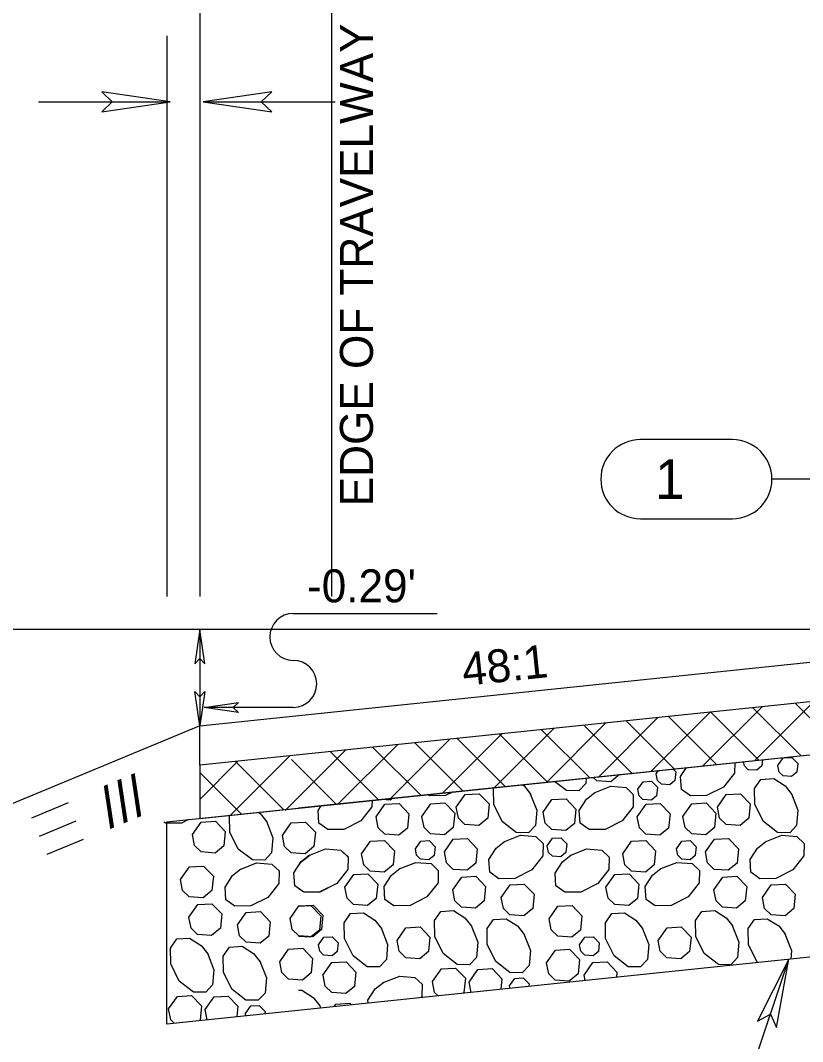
# Model space of a CAD drawing. Extents: x 6561 to 6787, y 19927 to 20919.
# Drawn here: x 6684.34 to 6696.19, y 20747.4 to 20762.88 of the extents above; entities that cross this region are included whole.
import ezdxf

# ---------------------------------------------------------------- set-up
doc = ezdxf.new("R2010")
doc.units = 0
for name, color, linetype in [('Level 1', 7, 'Continuous'), ('Level 3', 7, 'Continuous'), ('Level 5', 7, 'Continuous'), ('Level 7', 7, 'Continuous'), ('Level 8', 7, 'Continuous')]:
    doc.layers.add(name, color=color, linetype=linetype)

msp = doc.modelspace()

# ---------------------------------------------------------------- linework, layer by layer
at = {"layer": 'Level 1'}
for p, q in [((6687.057, 20764.65), (6687.057, 20754.15)), ((6689.057, 20764.65), (6689.057, 20754.15)), ((6686.557, 20762.65), (6686.557, 20754.15)), ((6684.612, 20761.65), (6686.612, 20761.65)), ((6687.112, 20761.65), (6689.112, 20761.65)), ((6688.476, 20753.894), (6690.658, 20753.894)), ((6779.047, 20753.65), (6628.473, 20753.65)), ((6687.057, 20753.65), (6687.057, 20752.192)), ((6688.476, 20752.47), (6687.127, 20752.47))]:
    msp.add_line(p, q, dxfattribs=at)
for points in [[(6686.612, 20761.65), (6685.573, 20761.8), (6685.733, 20761.65), (6685.573, 20761.5)], [(6687.112, 20761.65), (6688.151, 20761.5), (6687.991, 20761.65), (6688.151, 20761.8)], [(6687.057, 20753.65), (6686.985, 20753.13), (6687.059, 20753.211), (6687.135, 20753.131)], [(6687.057, 20752.192), (6686.985, 20752.711), (6687.059, 20752.631), (6687.135, 20752.711)], [(6687.127, 20752.47), (6687.647, 20752.542), (6687.566, 20752.467), (6687.646, 20752.392)]]:
    msp.add_lwpolyline(points, close=True, dxfattribs=at)
for centre, start, end in [((6688.476, 20753.538), 90, 270), ((6688.476, 20752.826), 270, 90)]:
    msp.add_arc(centre, 0.356, start, end, dxfattribs=at)
at = {"layer": 'Level 3'}
for p, q in [((6701.057, 20753.05), (6687.057, 20751.592)), ((6696.371, 20752.562), (6695.473, 20751.664)), ((6696.811, 20751.803), (6696.082, 20752.532)), ((6694.792, 20752.397), (6693.894, 20751.499)), ((6695.582, 20752.48), (6694.684, 20751.582)), ((6695.53, 20751.67), (6694.802, 20752.398)), ((6696.171, 20751.737), (6695.442, 20752.465)), ((6687.057, 20750.787), (6701.057, 20752.246)), ((6693.214, 20752.233), (6692.316, 20751.335)), ((6694.003, 20752.315), (6693.105, 20751.417)), ((6694.249, 20751.536), (6693.521, 20752.265)), ((6694.89, 20751.603), (6694.161, 20752.332)), ((6691.635, 20752.068), (6690.737, 20751.171)), ((6692.424, 20752.151), (6691.526, 20751.253)), ((6692.328, 20751.336), (6691.6, 20752.065)), ((6692.969, 20751.403), (6692.24, 20752.131)), ((6693.609, 20751.47), (6692.88, 20752.198)), ((6690.056, 20751.904), (6689.158, 20751.006)), ((6690.846, 20751.986), (6689.948, 20751.088)), ((6691.047, 20751.203), (6690.319, 20751.931)), ((6691.688, 20751.27), (6690.959, 20751.998)), ((6689.267, 20751.822), (6688.352, 20750.907)), ((6689.767, 20751.07), (6689.038, 20751.798)), ((6690.407, 20751.136), (6689.678, 20751.865)), ((6687.635, 20751.652), (6687.057, 20751.074)), ((6687.057, 20751.592), (6687.057, 20750.787)), ((6688.424, 20751.734), (6687.526, 20750.836)), ((6688.328, 20750.92), (6687.6, 20751.648)), ((6689.126, 20751.003), (6688.449, 20751.68)), ((6687.688, 20750.853), (6687.057, 20751.484))]:
    msp.add_line(p, q, dxfattribs=at)
at = {"layer": 'Level 5'}
for p, q in [((6686.557, 20750.735), (6701.057, 20752.246)), ((6688.557, 20750.944), (6701.057, 20752.246)), ((6686.557, 20747.669), (6686.557, 20750.735)), ((6701.057, 20749.179), (6686.557, 20747.669))]:
    msp.add_line(p, q, dxfattribs=at)
for points in [[(6695.166, 20751.632), (6695.163, 20751.474), (6694.996, 20751.261), (6694.738, 20751.133), (6694.496, 20751.128), (6694.359, 20751.225), (6694.346, 20751.419), (6694.434, 20751.556)], [(6695.588, 20751.676), (6695.578, 20751.582), (6695.499, 20751.516), (6695.371, 20751.525), (6695.312, 20751.583), (6695.299, 20751.646)], [(6695.822, 20751.588), (6695.902, 20751.703), (6696.031, 20751.71), (6696.121, 20751.617), (6696.108, 20751.487), (6696.028, 20751.421), (6695.901, 20751.43), (6695.841, 20751.488), (6695.822, 20751.588)], [(6693.418, 20751.45), (6693.287, 20751.341), (6693.075, 20751.356), (6693.021, 20751.408)], [(6693.974, 20751.462), (6694.009, 20751.511)], [(6694.232, 20751.535), (6694.273, 20751.491), (6694.261, 20751.361), (6694.181, 20751.295), (6694.054, 20751.304), (6693.994, 20751.362), (6693.975, 20751.462)], [(6691.944, 20751.296), (6691.973, 20751.278), (6692.074, 20751.151)], [(6692.915, 20751.398), (6692.908, 20751.313), (6692.804, 20751.203), (6692.616, 20751.207), (6692.436, 20751.348)], [(6693.697, 20751.229), (6693.778, 20751.343), (6693.907, 20751.351), (6693.996, 20751.258), (6693.983, 20751.128), (6693.904, 20751.062), (6693.776, 20751.071), (6693.716, 20751.129), (6693.697, 20751.229)], [(6696.025, 20751.161), (6696.125, 20750.91), (6696.105, 20750.679), (6696, 20750.569), (6695.813, 20750.572), (6695.6, 20750.739), (6695.471, 20750.997), (6695.467, 20751.239), (6695.564, 20751.376), (6695.757, 20751.389), (6695.93, 20751.278), (6696.031, 20751.151)], [(6690.889, 20751.186), (6690.781, 20751.133), (6690.538, 20751.128), (6690.512, 20751.147)], [(6690.946, 20750.956), (6691.08, 20751.148), (6691.295, 20751.16), (6691.444, 20751.005), (6691.423, 20750.788), (6691.29, 20750.678), (6691.078, 20750.694), (6690.978, 20750.79), (6690.946, 20750.956)], [(6692.068, 20751.161), (6692.167, 20750.91), (6692.147, 20750.679), (6692.043, 20750.569), (6691.855, 20750.572), (6691.642, 20750.739), (6691.514, 20750.997), (6691.509, 20751.239), (6691.518, 20751.252)], [(6693.037, 20751.174), (6693.288, 20751.274), (6693.519, 20751.254), (6693.629, 20751.149), (6693.626, 20750.962), (6693.459, 20750.749), (6693.201, 20750.62), (6692.959, 20750.616), (6692.822, 20750.713), (6692.809, 20750.906), (6692.92, 20751.079), (6693.047, 20751.181)], [(6694.903, 20750.956), (6695.038, 20751.148), (6695.252, 20751.16), (6695.402, 20751.005), (6695.38, 20750.788), (6695.247, 20750.678), (6695.035, 20750.694), (6694.936, 20750.79), (6694.903, 20750.956)], [(6689.67, 20751.059), (6689.668, 20750.962), (6689.501, 20750.749), (6689.244, 20750.62), (6689.001, 20750.616), (6688.864, 20750.713), (6688.852, 20750.906), (6688.898, 20750.979)], [(6689.731, 20750.808), (6689.865, 20751), (6690.08, 20751.012), (6690.229, 20750.857), (6690.207, 20750.64), (6690.075, 20750.53), (6689.863, 20750.545), (6689.763, 20750.642), (6689.731, 20750.808)], [(6689.983, 20751.092), (6689.946, 20751.062), (6689.819, 20751.071), (6689.815, 20751.075)], [(6690.424, 20750.816), (6690.559, 20751.007), (6690.773, 20751.02), (6690.923, 20750.865), (6690.901, 20750.648), (6690.769, 20750.538), (6690.557, 20750.553), (6690.457, 20750.65), (6690.424, 20750.816)], [(6692.261, 20750.879), (6692.396, 20751.071), (6692.61, 20751.083), (6692.76, 20750.928), (6692.738, 20750.711), (6692.605, 20750.601), (6692.393, 20750.616), (6692.294, 20750.713), (6692.261, 20750.879)], [(6693.688, 20750.808), (6693.823, 20751), (6694.037, 20751.012), (6694.186, 20750.857), (6694.165, 20750.64), (6694.032, 20750.53), (6693.82, 20750.545), (6693.721, 20750.642), (6693.688, 20750.808)], [(6694.382, 20750.816), (6694.516, 20751.007), (6694.731, 20751.02), (6694.88, 20750.865), (6694.859, 20750.648), (6694.726, 20750.538), (6694.514, 20750.553), (6694.414, 20750.65), (6694.382, 20750.816)], [(6688.068, 20750.745), (6688.167, 20750.493), (6688.147, 20750.262), (6688.043, 20750.152), (6687.855, 20750.156), (6687.642, 20750.322), (6687.514, 20750.58), (6687.509, 20750.823), (6687.518, 20750.835)], [(6687.944, 20750.88), (6687.973, 20750.862), (6688.074, 20750.735)], [(6686.889, 20750.77), (6686.781, 20750.716), (6686.538, 20750.712), (6686.512, 20750.73)], [(6686.946, 20750.54), (6687.08, 20750.731), (6687.295, 20750.743), (6687.444, 20750.589), (6687.423, 20750.372), (6687.29, 20750.261), (6687.078, 20750.277), (6686.978, 20750.374), (6686.946, 20750.54)], [(6688.312, 20750.527), (6688.446, 20750.718), (6688.661, 20750.73), (6688.81, 20750.576), (6688.789, 20750.359), (6688.656, 20750.249), (6688.444, 20750.264), (6688.344, 20750.361), (6688.312, 20750.527)], [(6691.669, 20750.43), (6691.92, 20750.53), (6692.151, 20750.51), (6692.261, 20750.406), (6692.258, 20750.218), (6692.091, 20750.005), (6691.833, 20749.876), (6691.591, 20749.872), (6691.454, 20749.969), (6691.441, 20750.162), (6691.552, 20750.335), (6691.679, 20750.437)], [(6695.626, 20750.43), (6695.878, 20750.53), (6696.109, 20750.51), (6696.219, 20750.406), (6696.215, 20750.218), (6696.048, 20750.005), (6695.791, 20749.876), (6695.548, 20749.872), (6695.412, 20749.969), (6695.399, 20750.162), (6695.509, 20750.335), (6695.636, 20750.437)], [(6689.51, 20750.248), (6689.645, 20750.44), (6689.859, 20750.452), (6690.008, 20750.297), (6689.987, 20750.08), (6689.854, 20749.97), (6689.642, 20749.985), (6689.543, 20750.082), (6689.51, 20750.248)], [(6690.326, 20750.327), (6690.407, 20750.442), (6690.535, 20750.449), (6690.625, 20750.356), (6690.612, 20750.226), (6690.532, 20750.16), (6690.405, 20750.169), (6690.345, 20750.227), (6690.326, 20750.327)], [(6690.767, 20750.277), (6690.901, 20750.469), (6691.116, 20750.481), (6691.265, 20750.326), (6691.243, 20750.109), (6691.111, 20749.999), (6690.899, 20750.014), (6690.799, 20750.111), (6690.767, 20750.277)], [(6692.323, 20750.371), (6692.403, 20750.486), (6692.532, 20750.493), (6692.622, 20750.4), (6692.609, 20750.27), (6692.529, 20750.204), (6692.402, 20750.213), (6692.342, 20750.271), (6692.323, 20750.371)], [(6693.468, 20750.248), (6693.602, 20750.44), (6693.817, 20750.452), (6693.966, 20750.297), (6693.944, 20750.08), (6693.812, 20749.97), (6693.6, 20749.985), (6693.5, 20750.082), (6693.468, 20750.248)], [(6694.283, 20750.327), (6694.364, 20750.442), (6694.493, 20750.449), (6694.582, 20750.356), (6694.569, 20750.226), (6694.49, 20750.16), (6694.363, 20750.169), (6694.303, 20750.227), (6694.283, 20750.327)], [(6694.724, 20750.277), (6694.858, 20750.469), (6695.073, 20750.481), (6695.222, 20750.326), (6695.201, 20750.109), (6695.068, 20749.999), (6694.856, 20750.014), (6694.756, 20750.111), (6694.724, 20750.277)], [(6688.712, 20750.226), (6688.964, 20750.326), (6689.195, 20750.306), (6689.305, 20750.202), (6689.301, 20750.014), (6689.134, 20749.801), (6688.877, 20749.672), (6688.634, 20749.668), (6688.498, 20749.765), (6688.485, 20749.959), (6688.595, 20750.131), (6688.722, 20750.233)], [(6688.713, 20750.224), (6688.965, 20750.323), (6689.196, 20750.304), (6689.306, 20750.199), (6689.302, 20750.012), (6689.136, 20749.799), (6688.878, 20749.67), (6688.635, 20749.666), (6688.557, 20749.721)], [(6688.557, 20750.067), (6688.597, 20750.129), (6688.724, 20750.23)], [(6692.671, 20750.224), (6692.922, 20750.323), (6693.154, 20750.304), (6693.263, 20750.199), (6693.26, 20750.012), (6693.093, 20749.799), (6692.836, 20749.67), (6692.593, 20749.666), (6692.456, 20749.763), (6692.443, 20749.956), (6692.554, 20750.129), (6692.681, 20750.23)], [(6686.767, 20749.861), (6686.901, 20750.052), (6687.116, 20750.064), (6687.265, 20749.909), (6687.243, 20749.693), (6687.111, 20749.582), (6686.899, 20749.598), (6686.799, 20749.694), (6686.767, 20749.861)], [(6687.669, 20750.014), (6687.92, 20750.113), (6688.151, 20750.093), (6688.261, 20749.989), (6688.258, 20749.801), (6688.091, 20749.588), (6687.833, 20749.46), (6687.591, 20749.455), (6687.454, 20749.552), (6687.441, 20749.746), (6687.552, 20749.919), (6687.679, 20750.02)], [(6690.08, 20750.02), (6690.332, 20750.12), (6690.563, 20750.1), (6690.672, 20749.996), (6690.669, 20749.808), (6690.502, 20749.595), (6690.245, 20749.466), (6690.002, 20749.462), (6689.865, 20749.559), (6689.852, 20749.753), (6689.963, 20749.926), (6690.09, 20750.027)], [(6694.037, 20750.02), (6694.289, 20750.12), (6694.52, 20750.1), (6694.63, 20749.996), (6694.626, 20749.808), (6694.46, 20749.595), (6694.202, 20749.466), (6693.959, 20749.462), (6693.823, 20749.559), (6693.81, 20749.753), (6693.921, 20749.926), (6694.048, 20750.027)], [(6689.257, 20749.742), (6689.392, 20749.934), (6689.606, 20749.946), (6689.755, 20749.791), (6689.734, 20749.574), (6689.601, 20749.464), (6689.389, 20749.479), (6689.29, 20749.576), (6689.257, 20749.742)], [(6690.893, 20749.705), (6691.028, 20749.896), (6691.242, 20749.908), (6691.391, 20749.754), (6691.37, 20749.537), (6691.237, 20749.426), (6691.025, 20749.442), (6690.926, 20749.538), (6690.893, 20749.705)], [(6693.215, 20749.742), (6693.349, 20749.934), (6693.564, 20749.946), (6693.713, 20749.791), (6693.691, 20749.574), (6693.559, 20749.464), (6693.347, 20749.479), (6693.247, 20749.576), (6693.215, 20749.742)], [(6694.85, 20749.705), (6694.985, 20749.896), (6695.2, 20749.908), (6695.349, 20749.754), (6695.327, 20749.537), (6695.195, 20749.426), (6694.983, 20749.442), (6694.883, 20749.538), (6694.851, 20749.705)], [(6691.628, 20749.588), (6691.763, 20749.779), (6691.977, 20749.791), (6692.127, 20749.636), (6692.105, 20749.42), (6691.972, 20749.309), (6691.76, 20749.325), (6691.661, 20749.421), (6691.628, 20749.588)], [(6695.586, 20749.588), (6695.72, 20749.779), (6695.935, 20749.791), (6696.084, 20749.636), (6696.062, 20749.42), (6695.93, 20749.309), (6695.718, 20749.325), (6695.618, 20749.421), (6695.586, 20749.588)], [(6686.893, 20749.288), (6687.028, 20749.479), (6687.242, 20749.492), (6687.391, 20749.337), (6687.37, 20749.12), (6687.237, 20749.01), (6687.025, 20749.025), (6686.926, 20749.122), (6686.893, 20749.288)], [(6688.427, 20749.268), (6688.561, 20749.459), (6688.776, 20749.471), (6688.925, 20749.317), (6688.904, 20749.1), (6688.771, 20748.99), (6688.559, 20749.005), (6688.459, 20749.102), (6688.427, 20749.268)], [(6688.557, 20749.455), (6688.744, 20749.466), (6688.893, 20749.311), (6688.872, 20749.094), (6688.739, 20748.984), (6688.557, 20748.997)], [(6692.352, 20749.262), (6692.487, 20749.454), (6692.701, 20749.466), (6692.851, 20749.311), (6692.829, 20749.094), (6692.696, 20748.984), (6692.485, 20748.999), (6692.385, 20749.096), (6692.352, 20749.262)], [(6687.628, 20749.171), (6687.763, 20749.362), (6687.977, 20749.374), (6688.127, 20749.22), (6688.105, 20749.003), (6687.972, 20748.893), (6687.76, 20748.908), (6687.661, 20749.005), (6687.628, 20749.171)], [(6689.806, 20749.127), (6689.906, 20748.876), (6689.886, 20748.645), (6689.782, 20748.535), (6689.594, 20748.538), (6689.381, 20748.705), (6689.252, 20748.963), (6689.248, 20749.205), (6689.345, 20749.342), (6689.539, 20749.355), (6689.712, 20749.244), (6689.813, 20749.117)], [(6691.173, 20749.16), (6691.273, 20748.908), (6691.253, 20748.677), (6691.148, 20748.567), (6690.961, 20748.571), (6690.748, 20748.738), (6690.619, 20748.995), (6690.615, 20749.238), (6690.712, 20749.375), (6690.905, 20749.388), (6691.078, 20749.277), (6691.179, 20749.15)], [(6691.97, 20749.038), (6692.07, 20748.786), (6692.05, 20748.555), (6691.945, 20748.445), (6691.758, 20748.449), (6691.545, 20748.616), (6691.416, 20748.873), (6691.412, 20749.116), (6691.509, 20749.253), (6691.702, 20749.266), (6691.875, 20749.155), (6691.976, 20749.028)], [(6693.764, 20749.127), (6693.864, 20748.876), (6693.844, 20748.645), (6693.739, 20748.535), (6693.552, 20748.538), (6693.339, 20748.705), (6693.21, 20748.963), (6693.206, 20749.205), (6693.303, 20749.342), (6693.496, 20749.355), (6693.669, 20749.244), (6693.77, 20749.117)], [(6695.13, 20749.16), (6695.23, 20748.908), (6695.21, 20748.677), (6695.106, 20748.567), (6694.918, 20748.571), (6694.705, 20748.738), (6694.576, 20748.995), (6694.572, 20749.238), (6694.669, 20749.375), (6694.863, 20749.388), (6695.035, 20749.277), (6695.137, 20749.15)], [(6695.519, 20748.602), (6695.502, 20748.616), (6695.373, 20748.873), (6695.369, 20749.116), (6695.466, 20749.253), (6695.66, 20749.266), (6695.833, 20749.155), (6695.934, 20749.028)], [(6690.048, 20748.937), (6690.182, 20749.128), (6690.397, 20749.141), (6690.546, 20748.986), (6690.525, 20748.769), (6690.392, 20748.659), (6690.18, 20748.674), (6690.08, 20748.771), (6690.048, 20748.937)], [(6694.005, 20748.937), (6694.14, 20749.128), (6694.354, 20749.141), (6694.504, 20748.986), (6694.482, 20748.769), (6694.349, 20748.659), (6694.137, 20748.674), (6694.038, 20748.771), (6694.005, 20748.937)], [(6687.173, 20748.743), (6687.273, 20748.492), (6687.253, 20748.261), (6687.148, 20748.151), (6686.961, 20748.154), (6686.748, 20748.321), (6686.619, 20748.579), (6686.615, 20748.821), (6686.712, 20748.958), (6686.905, 20748.971), (6687.078, 20748.86), (6687.179, 20748.733)], [(6688.857, 20748.87), (6688.938, 20748.985), (6689.066, 20748.993), (6689.156, 20748.9), (6689.143, 20748.77), (6689.063, 20748.703), (6688.936, 20748.713), (6688.876, 20748.771), (6688.857, 20748.87)], [(6692.814, 20748.87), (6692.895, 20748.985), (6693.024, 20748.993), (6693.113, 20748.9), (6693.1, 20748.77), (6693.021, 20748.703), (6692.894, 20748.713), (6692.834, 20748.771), (6692.814, 20748.87)], [(6695.927, 20749.038), (6696.027, 20748.786), (6696.016, 20748.654)], [(6687.97, 20748.621), (6688.07, 20748.37), (6688.05, 20748.139), (6687.945, 20748.029), (6687.758, 20748.032), (6687.545, 20748.199), (6687.416, 20748.457), (6687.412, 20748.699), (6687.509, 20748.836), (6687.702, 20748.849), (6687.875, 20748.738), (6687.976, 20748.611)], [(6688.27, 20748.614), (6688.404, 20748.805), (6688.619, 20748.817), (6688.768, 20748.663), (6688.746, 20748.446), (6688.614, 20748.336), (6688.402, 20748.351), (6688.302, 20748.448), (6688.27, 20748.614)], [(6692.315, 20748.598), (6692.449, 20748.789), (6692.664, 20748.802), (6692.813, 20748.647), (6692.791, 20748.43), (6692.659, 20748.32), (6692.447, 20748.335), (6692.347, 20748.432), (6692.315, 20748.598)], [(6688.925, 20748.408), (6689.06, 20748.6), (6689.275, 20748.612), (6689.424, 20748.457), (6689.402, 20748.24), (6689.27, 20748.13), (6689.058, 20748.145), (6688.958, 20748.242), (6688.926, 20748.408)], [(6690.586, 20748.314), (6690.72, 20748.505), (6690.935, 20748.517), (6691.084, 20748.362), (6691.063, 20748.146), (6691.052, 20748.137)], [(6691.139, 20748.305), (6691.274, 20748.497), (6691.488, 20748.509), (6691.637, 20748.354), (6691.622, 20748.196)], [(6692.883, 20748.408), (6693.017, 20748.6), (6693.232, 20748.612), (6693.381, 20748.457), (6693.373, 20748.379)], [(6689.836, 20748.296), (6690.088, 20748.396), (6690.319, 20748.376), (6690.428, 20748.271), (6690.425, 20748.084), (6690.414, 20748.07)], [(6691.751, 20748.246), (6691.832, 20748.361), (6691.96, 20748.368), (6692.05, 20748.276), (6692.046, 20748.24)], [(6692.898, 20748.329), (6692.883, 20748.408)], [(6688.557, 20748.181), (6688.603, 20748.184), (6688.776, 20748.073), (6688.877, 20747.946)], [(6689.611, 20747.987), (6689.608, 20748.028), (6689.719, 20748.201), (6689.846, 20748.302)], [(6690.67, 20748.097), (6690.618, 20748.147), (6690.586, 20748.313)], [(6691.17, 20748.149), (6691.139, 20748.305)], [(6691.758, 20748.21), (6691.751, 20748.246)], [(6686.586, 20747.897), (6686.72, 20748.088), (6686.935, 20748.1), (6687.084, 20747.946), (6687.063, 20747.729), (6687.052, 20747.72)], [(6687.139, 20747.889), (6687.274, 20748.08), (6687.488, 20748.092), (6687.637, 20747.938), (6687.622, 20747.78)], [(6686.67, 20747.68), (6686.618, 20747.731), (6686.586, 20747.897)], [(6687.17, 20747.732), (6687.139, 20747.889)], [(6687.751, 20747.83), (6687.832, 20747.944), (6687.96, 20747.952), (6688.05, 20747.859), (6688.046, 20747.824)], [(6688.871, 20747.956), (6688.889, 20747.912)], [(6689.093, 20747.933), (6689.12, 20747.97), (6689.334, 20747.983), (6689.356, 20747.96)], [(6687.758, 20747.794), (6687.751, 20747.83)]]:
    msp.add_lwpolyline(points, dxfattribs=at)
at = {"layer": 'Level 7'}
msp.add_line((6687.057, 20752.192), (6679.057, 20748.858), dxfattribs=at)
for points in [[(6684.514, 20750.795), (6685.068, 20751.026)], [(6684.629, 20750.519), (6685.183, 20750.749)], [(6684.744, 20750.242), (6685.298, 20750.473)]]:
    msp.add_lwpolyline(points, dxfattribs=at)
at = {"layer": 'Level 8'}
for p, q in [((6695.131, 20756.529), (6693.737, 20756.529)), ((6696.539, 20755.929), (6695.731, 20755.929)), ((6693.737, 20755.329), (6695.131, 20755.329)), ((6687.057, 20752.192), (6701.057, 20753.65)), ((6701.057, 20753.05), (6687.057, 20751.592)), ((6687.057, 20751.592), (6687.057, 20752.192)), ((6694.977, 20745.628), (6695.984, 20748.651))]:
    msp.add_line(p, q, dxfattribs=at)
msp.add_lwpolyline([(6695.984, 20748.651), (6695.513, 20747.713), (6695.706, 20747.817), (6695.798, 20747.618)], close=True, dxfattribs=at)
for centre, start, end in [((6693.737, 20755.929), 90, 270), ((6695.131, 20755.929), 270, 90)]:
    msp.add_arc(centre, 0.6, start, end, dxfattribs=at)

# ---------------------------------------------------------------- texts
at = {"layer": 'Level 1'}
for s, rotation, p in [('EDGE OF TRAVELWAY', 90, (6689.683, 20755.519)), ('48:1', 5.9469, (6691.059, 20752.794))]:
    msp.add_text(s, height=0.5, rotation=rotation, dxfattribs=at).set_placement(p)
msp.add_text("-0.29'", height=0.5, dxfattribs=at).set_placement((6688.684, 20754.062))
at = {"layer": 'Level 7'}
msp.add_text('///', height=0.6, rotation=22.6195, dxfattribs=at).set_placement((6685.698, 20750.633))
at = {"layer": 'Level 8'}
msp.add_text(' 1', height=0.6, dxfattribs=at).set_placement((6693.737, 20755.629))

doc.saveas('drawing.dxf')
